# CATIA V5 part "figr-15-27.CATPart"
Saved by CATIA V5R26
Part number: Part1
Bounding box of the stored display mesh (mm): x -61.282 to 61.282, y -26.72 to 26.72, z 0 to 0.75
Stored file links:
  D:\_Deepak\CATIA\CATIA V5-6R2016_Deepak\Resources\Part files\Partfiles\c15_catia_v5_6r2016_prt\figr-15-27.CATPart
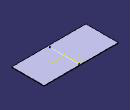
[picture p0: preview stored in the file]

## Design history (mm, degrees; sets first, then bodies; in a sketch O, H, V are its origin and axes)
SheetMetalParameters1: Thickness 0.75, BendRadius 1, KFactor 0.356492 {= log(min(100,max(20*SheetMetalParameters1.BendRadius,SheetMetalParameters1.Thickness)/SheetMetalParameters1.Thickness))/log(100)/2}, ReliefRadialLength 1, ReliefAxialLength 2, MinimumBendRadius 0
Body1 (main body)
  Sketch1 on xy-plane, origin (0, 0, 0), H (1, 0, 0), V (0, 1, 0)
    line L1 (61.282, 26.7197) -> (61.282, -26.7197)
    line L2 (61.282, -26.7197) -> (-61.282, -26.7197)
    line L3 (-61.282, -26.7197) -> (-61.282, 26.7197)
    line L4 (-61.282, 26.7197) -> (61.282, 26.7197)
    vertical: L1 V, L3 V
    horizontal: L2 H, L4 H
    equidistance: L1 L3 O, L2 L4 O
  Wall1: Thickness 0.75, Profile Sketch1
  Sketch2 on face of Wall1, origin (0, 0, 0.75), H (1, 0, 0), V (0, 1, 0)
    line L1 (1.9015, 25.4615) -> (1.9015, -22.9675)
    vertical: L1 V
